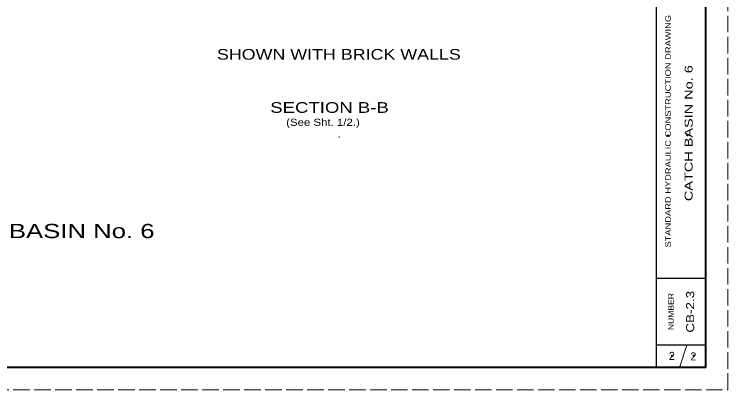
# Model space of a CAD drawing. Extents: x 1083.1 to 1117.1, y 719.4 to 763.4.
# Drawn here: x 1101.09 to 1117.13, y 719.35 to 727.78 of the extents above; entities that cross this region are included whole.
import ezdxf
from ezdxf.enums import TextEntityAlignment as Align

# ---------------------------------------------------------------- set-up
doc = ezdxf.new("R2010")
doc.units = 0
doc.header["$LTSCALE"] = 0.062
doc.header["$PDMODE"] = 32
doc.header["$PDSIZE"] = 0.031
doc.linetypes.add('LONG_DASHED', pattern=[7.5, 6, -1.5])
doc.layers.add('1', color=7, linetype='Continuous', lineweight=13)

msp = doc.modelspace()

# ---------------------------------------------------------------- linework, layer by layer
at = {"layer": '1', "lineweight": 25}
for p, q in [((1115.52642, 719.85408), (1115.52642, 740.85408)), ((1116.62642, 740.85408), (1116.62642, 719.85408)), ((1116.62642, 721.85408), (1115.52642, 721.85408)), ((1116.62642, 720.35408), (1115.52642, 720.35408))]:
    msp.add_line(p, q, dxfattribs=at)
at = {"layer": '1', "linetype": 'LONG_DASHED'}
msp.add_line((1108.38908, 725.01825), (1108.38908, 725.04167), dxfattribs=at)
at = {"layer": '1'}
msp.add_line((1116.04308, 719.85408), (1116.20975, 720.35408), dxfattribs=at)
at = {"layer": '1', "linetype": 'LONG_DASHED'}
msp.add_lwpolyline([(1083.12642, 719.35408), (1117.12642, 719.35408), (1117.12642, 741.35408), (1083.12642, 741.35408)], close=True, dxfattribs=at)
at = {"layer": '1', "lineweight": 25}
msp.add_lwpolyline([(1116.62642, 719.85408), (1085.12642, 719.85408), (1085.12642, 740.85408)], dxfattribs=at)
at = {"layer": '1', "lineweight": 40}
msp.add_lwpolyline([(1085.12642, 740.85408), (1116.62642, 740.85408), (1116.62642, 719.85408), (1085.12642, 719.85408)], close=True, dxfattribs=at)
msp.add_lwpolyline([(1085.12642, 740.85408), (1116.62642, 740.85408), (1116.62642, 719.85408), (1085.12642, 719.85408)], close=True, dxfattribs=at)
at = {"layer": '1'}
for p in [(1115.78383, 725.06008), (1116.21667, 725.06742), (1115.8745, 720.11783), (1116.36292, 720.11683)]:
    msp.add_point(p, dxfattribs=at)

# ---------------------------------------------------------------- texts
for s, height, width, p in [('STANDARD HYDRAULIC CONSTRUCTION DRAWING', 0.125, 1.25, (1115.84633, 725.15812)), ('CATCH BASIN No. 6', 0.18, 1.35, (1116.337, 725.11425)), ('NUMBER', 0.125, 1.15, (1115.91342, 721.10817)), ('CB-2.3', 0.18, 1.25, (1116.37158, 721.10438))]:
    msp.add_text(s, height=height, rotation=90, dxfattribs=dict(at, width=width)).set_placement(p, align=Align.CENTER)
for s, height, width, p in [('SHOWN WITH BRICK WALLS', 0.24, 1.25, (1105.64183, 726.76392)), ('SECTION B-B', 0.24, 1.3, (1106.84133, 725.57033)), ('(See Sht. 1/2.)', 0.16, 1.2, (1107.19883, 725.27842))]:
    msp.add_text(s, height=height, dxfattribs=dict(at, width=width)).set_placement(p)
at = {"layer": '1', "width": 1.35}
msp.add_text('CATCH BASIN No. 6', height=0.32, dxfattribs=at).set_placement((1101.52717, 722.757), align=Align.CENTER)
at = {"layer": '1'}
for p in [(1115.87088, 720.02417), (1116.35371, 720.01158)]:
    msp.add_text('2', height=0.18, dxfattribs=at).set_placement(p, align=Align.CENTER)

doc.saveas('drawing.dxf')
